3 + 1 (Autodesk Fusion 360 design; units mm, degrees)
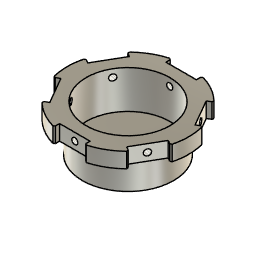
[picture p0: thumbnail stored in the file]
sketch "Sketch1" plane through (0, 0, 0) normal (0, 0, 1) x axis (1, 0, 0)
  circle C1 centre (0, 0) radius 38.1
  point P1 (0, 0)
  point P2 (0, 0)
  coincident P1 P2
  dimension "d1" diameter C1 = 76.2
extrude "Extrude1" new body sketch "Sketch1" along normal blind 25.4 bodies "Part"
sketch "Sketch2" plane through (0, 0, 25.4) normal (0, 0, 1) x axis (-1, 0, 0)
  circle C1 centre (0, 0) radius 38.1
  circle C2 centre (0, 0) radius 50.8
  point P1 (0, 0)
  point P3 (0, 0)
  coincident P1 P3
  dimension "d4" diameter C2 = 101.6
extrude "Extrude2" add sketch "Sketch2" along normal blind 12.7
sketch "Sketch5" plane through (0, 0, 38.1) normal (0, 0, 1) x axis (-1, 0, 0)
  circle C1 centre (0, 0) radius 34.925
  circle C2 centre (0, 0) radius 50.8
  concentric C1 C2
  dimension "d16" diameter C1 = 69.85
extrude "Extrude4" cut sketch "Sketch5" profile of C1 against normal blind 31.75
copy_paste_bodies "CopyPasteBodies1"
sketch "Sketch3" plane through (0, 0, 25.4) normal (0, 0, -1) x axis (1, 0, 0)
  line L1 (-12.7, 44.45) -> (12.7, 44.45)
  line L2 (-12.7, 57.15) -> (-12.7, 44.45)
  line L3 (12.7, 57.15) -> (-12.7, 57.15)
  line L4 (12.7, 44.45) -> (12.7, 57.15)
  line L5 (-12.7, 57.15) -> (12.7, 44.45)
  line L6 (12.7, 57.15) -> (-12.7, 44.45)
  circle C1 centre (0, 0) radius 50.8
  circle C2 centre (0, 0) radius 38.1
  point P7 (0, 50.8)
  point P1 (0, 0)
  point P5 (-12.7, 57.15)
  point P6 (12.7, 57.15)
  point P3 (12.7, 44.45)
  horizontal L1
  perpendicular L1 L2
  parallel L1 L3
  parallel L2 L4
  coincident L5 P7
  coincident L6 P7
  coincident C1 P7
  vertical P1 P7
  dimension "d7" distance P5 P6 = 25.4
  dimension "d8" distance P3 P6 = 12.7
extrude "Extrude3" cut sketch "Sketch3" profile of C1 L1 L2 L3 L4 no distance stored
sketch "Sketch4" plane through (0, -44.45, 0) normal (0, -1, 0) x axis (1, 0, 0)
  line L1 (-12.7, 38.1) -> (12.7, 38.1)
  line L2 (-12.7, 25.4) -> (-12.7, 38.1)
  line L3 (12.7, 25.4) -> (-12.7, 25.4)
  line L4 (12.7, 38.1) -> (12.7, 25.4)
  line L5 (12.7, 38.1) -> (-12.7, 25.4)
  point P4 (-12.7, 25.4)
  point P6 (-12.7, 25.4)
  point P2 (12.7, 38.1)
  point P7 (12.7, 38.1)
  point P8 (0, 31.75)
  coincident P4 P6
  coincident P2 P7
  midpoint L5 P8
hole "Hole1" HoleDepth 25.4 HoleDiameter 5.1054 TipAngle 118
chamfer "Chamfer1" distance 1.27
circular_pattern "C-Pattern1" TotalAngle 360
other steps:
base_feature "Base Feature" bodies "Stock"
thread "Thread2" ThreadOffset 0 ThreadDepth 10.0076
named bodies: "Part", "Stock"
